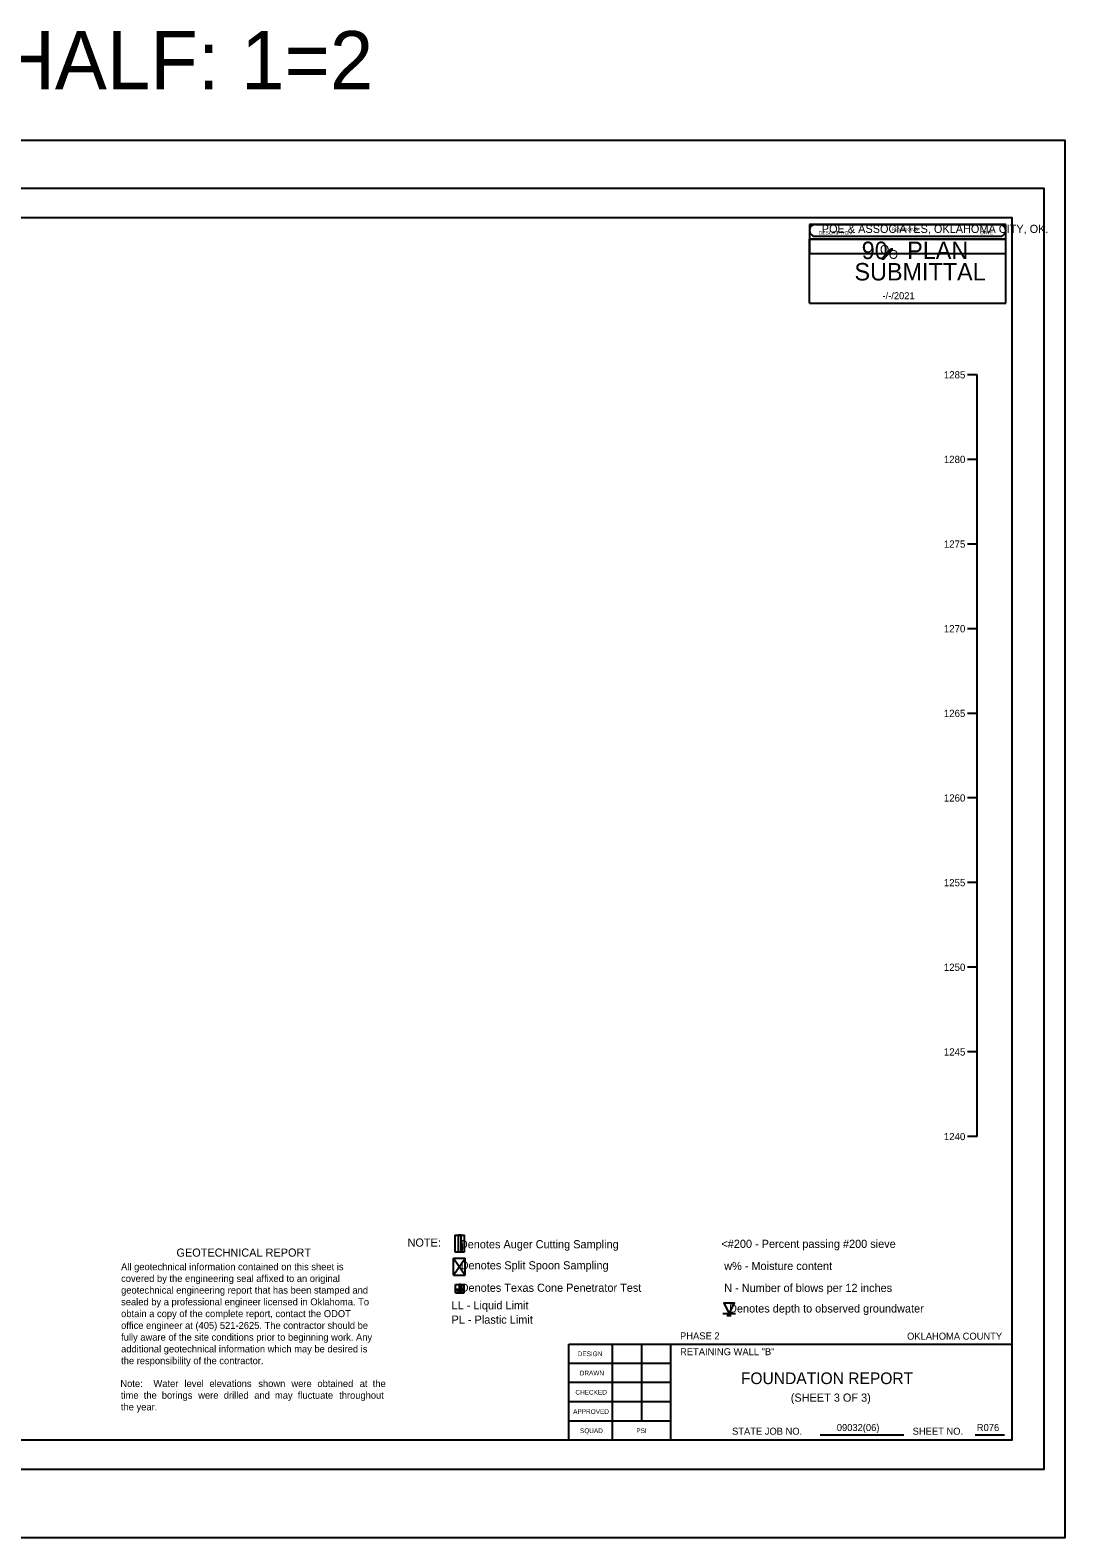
# Model space of a CAD drawing. Extents: x 7 to 126, y 24 to 56.
# Drawn here: x 107.93 to 125.68, y 30.33 to 56.22 of the extents above; entities that cross this region are included whole.
import ezdxf

# ---------------------------------------------------------------- set-up
doc = ezdxf.new("R2010")
doc.units = 0
for name, color, linetype in [('4', 7, 'Continuous'), ('S', 7, 'Continuous'), ('SHT_Plot_Shape_Full', 7, 'Continuous'), ('SHT_Plot_Shape_Half', 7, 'Continuous'), ('SHT_Sheet_Border', 7, 'Continuous'), ('SHT_Stamp_90_Submit', 7, 'Continuous'), ('SHT_Stamp_Rev_Block', 7, 'Continuous'), ('SHT_Standard_Sheet_Lines', 7, 'Continuous'), ('SHT_Standard_Sheet_Txt', 7, 'Continuous'), ('T', 7, 'Continuous'), ('T-5', 7, 'Continuous'), ('Text', 7, 'Continuous')]:
    doc.layers.add(name, color=color, linetype=linetype)

# ---------------------------------------------------------------- blocks, each defined once
blk = doc.blocks.new('DGRFC_WTLEV1_1')
for points in [[(-0.005, 0), (0.005, 0)], [(0, 0), (0.0042, 0.0083), (-0.0042, 0.0083), (0, 0)], [(-0.0017, -0.0017), (0.0017, -0.0017)]]:
    blk.add_lwpolyline(points)

msp = doc.modelspace()

# ---------------------------------------------------------------- linework, layer by layer
for p, q in [((124.178, 37.223), (124.178, 50.304)), ((115.214, 35.532), (115.214, 35.242))]:
    msp.add_line(p, q)
for points in [[(124.178, 50.304), (124.011, 50.304)], [(124.178, 48.851), (124.011, 48.851)], [(124.178, 47.397), (124.011, 47.397)], [(124.178, 45.944), (124.011, 45.944)], [(124.178, 44.49), (124.011, 44.49)], [(124.178, 43.037), (124.011, 43.037)], [(124.178, 41.583), (124.011, 41.583)], [(124.178, 40.13), (124.011, 40.13)], [(124.178, 38.676), (124.011, 38.676)], [(124.178, 37.223), (124.011, 37.223)], [(115.214, 35.532), (115.381, 35.532)], [(115.381, 35.242), (115.381, 35.532)], [(115.214, 35.242), (115.381, 35.242)], [(115.214, 35.242), (115.381, 35.242)]]:
    msp.add_lwpolyline(points)
for points in [[(115.272, 35.532), (115.272, 35.242), (115.322, 35.242), (115.322, 35.532)], [(115.337, 35.366), (115.331, 35.407), (115.322, 35.447), (115.337, 35.366)], [(115.322, 35.447), (115.322, 35.242), (115.337, 35.366), (115.322, 35.447)], [(115.322, 35.242), (115.337, 35.282), (115.337, 35.366), (115.322, 35.242)], [(115.322, 35.242), (115.331, 35.242), (115.337, 35.282), (115.322, 35.242)], [(115.337, 35.282), (115.339, 35.324), (115.337, 35.366), (115.337, 35.282)]]:
    msp.add_lwpolyline(points, close=True)
at = {"layer": 'SHT_Plot_Shape_Full'}
msp.add_lwpolyline([(89.683, 54.332), (125.683, 54.332), (125.683, 30.332), (89.683, 30.332)], close=True, dxfattribs=at)
at = {"layer": 'SHT_Plot_Shape_Half'}
msp.add_lwpolyline([(91.321, 53.507), (125.321, 53.507), (125.321, 31.507), (91.321, 31.507)], close=True, dxfattribs=at)
at = {"layer": 'SHT_Sheet_Border'}
for p, q in [((118.921, 32.007), (118.921, 33.658)), ((117.171, 32.007), (117.171, 33.657)), ((117.171, 33.657), (124.771, 33.657))]:
    msp.add_line(p, q, dxfattribs=at)
msp.add_lwpolyline([(93.271, 53.007), (124.771, 53.007), (124.771, 32.007), (93.271, 32.007)], close=True, dxfattribs=at)
at = {"layer": 'SHT_Stamp_90_Submit'}
for p, q in [((121.402, 52.883), (124.568, 52.883)), ((121.302, 52.633), (124.668, 52.633)), ((121.302, 51.534), (121.302, 52.633)), ((121.402, 52.683), (124.568, 52.683)), ((124.668, 51.534), (124.668, 52.633)), ((122.545, 52.295), (122.7, 52.467)), ((122.563, 52.295), (122.718, 52.467)), ((122.568, 52.295), (122.723, 52.467)), ((122.576, 52.295), (122.731, 52.467)), ((122.7, 52.467), (122.731, 52.467)), ((122.545, 52.295), (122.576, 52.295)), ((121.302, 51.534), (124.668, 51.534))]:
    msp.add_line(p, q, dxfattribs=at)
for centre, start, end in [((121.402, 52.783), 89.9952, 270), ((124.568, 52.783), 270, 90.0048)]:
    msp.add_arc(centre, 0.1, start, end, dxfattribs=at)
at = {"layer": 'SHT_Stamp_Rev_Block'}
for p, q in [((121.302, 52.883), (121.302, 52.383)), ((124.668, 52.883), (121.302, 52.883)), ((124.668, 52.383), (124.668, 52.883)), ((124.668, 52.633), (121.302, 52.633)), ((124.668, 52.383), (121.302, 52.383))]:
    msp.add_line(p, q, dxfattribs=at)
at = {"layer": 'SHT_Standard_Sheet_Lines'}
for p, q in [((117.921, 32.007), (117.921, 33.658)), ((118.421, 32.337), (118.421, 33.658)), ((121.482, 32.103), (122.922, 32.103)), ((124.146, 32.103), (124.649, 32.103))]:
    msp.add_line(p, q, dxfattribs=at)
for points in [[(118.921, 33.327), (117.171, 33.327)], [(118.921, 32.997), (117.171, 32.997)], [(118.921, 32.667), (117.171, 32.667)], [(118.921, 32.337), (117.171, 32.337)]]:
    msp.add_lwpolyline(points, dxfattribs=at)
at = {"layer": 'Text'}
for p, q in [((115.19, 34.841), (115.19, 35.134)), ((115.226, 34.542), (115.226, 34.682))]:
    msp.add_line(p, q, dxfattribs=at)
for points in [[(115.19, 34.841), (115.39, 35.134)], [(115.19, 35.134), (115.39, 34.841)], [(115.19, 35.134), (115.39, 35.134)], [(115.39, 34.841), (115.39, 35.134)], [(115.19, 34.841), (115.39, 34.841)], [(115.226, 34.682), (115.376, 34.682)], [(115.226, 34.542), (115.376, 34.542)], [(115.376, 34.542), (115.376, 34.682)]]:
    msp.add_lwpolyline(points, dxfattribs=at)
for points in [[(115.286, 34.598), (115.226, 34.598), (115.301, 34.542), (115.286, 34.598)], [(115.286, 34.598), (115.316, 34.682), (115.286, 34.682), (115.286, 34.598)], [(115.286, 34.598), (115.316, 34.598), (115.316, 34.682), (115.286, 34.598)], [(115.286, 34.598), (115.301, 34.542), (115.316, 34.598), (115.286, 34.598)], [(115.301, 34.542), (115.376, 34.598), (115.316, 34.598), (115.301, 34.542)]]:
    msp.add_lwpolyline(points, close=True, dxfattribs=at)

# ---------------------------------------------------------------- block references
at = {"layer": 'Text', "xscale": 21.6, "yscale": 21.6}
msp.add_blockref('DGRFC_WTLEV1_1', (119.922, 34.184), dxfattribs=at)

# ---------------------------------------------------------------- texts
for s, p in [('1285', (123.607, 50.242)), ('1280', (123.607, 48.789)), ('1275', (123.607, 47.335)), ('1270', (123.607, 45.882)), ('1265', (123.607, 44.428)), ('1260', (123.607, 42.975)), ('1255', (123.607, 41.521)), ('1250', (123.607, 40.068)), ('1245', (123.607, 38.614)), ('1240', (123.607, 37.161))]:
    msp.add_text(s, height=0.124).set_placement(p)
at = {"layer": '4'}
msp.add_text('FOUNDATION REPORT', height=0.2, dxfattribs=at).set_placement((120.124, 32.972))
at = {"layer": 'S'}
msp.add_text('FULL: 1=1   HALF: 1=2', height=1, dxfattribs=at).set_placement((99.989, 55.207))
at = {"layer": 'SHT_Stamp_90_Submit'}
for s, height, p in [('POE & ASSOCIATES, OKLAHOMA CITY, OK.', 0.14, (121.512, 52.74)), ('90   PLAN', 0.3, (122.197, 52.291)), ('O', 0.153, (122.511, 52.38)), ('O', 0.153, (122.662, 52.295)), ('SUBMITTAL', 0.3, (122.073, 51.924)), ('-/-/2021', 0.12, (122.553, 51.602))]:
    msp.add_text(s, height=height, dxfattribs=at).set_placement(p)
at = {"layer": 'SHT_Stamp_Rev_Block'}
for s, height, p in [('REVISIONS', 0.06, (122.71, 52.77)), ('DESCRIPTION', 0.05999, (121.462, 52.711)), ('DATE', 0.06, (124.231, 52.715))]:
    msp.add_text(s, height=height, dxfattribs=at).set_placement(p)
at = {"layer": 'SHT_Standard_Sheet_Txt'}
for s, height, p in [('DESIGN', 0.08, (117.323, 33.452)), ('DRAWN', 0.08, (117.358, 33.122)), ('CHECKED', 0.08, (117.284, 32.792)), ('APPROVED', 0.08, (117.245, 32.461)), ('SQUAD', 0.08, (117.362, 32.131)), ('PSI', 0.08, (118.329, 32.132)), ('STATE JOB NO.', 0.12, (119.972, 32.103)), ('SHEET NO. ', 0.12, (123.072, 32.103))]:
    msp.add_text(s, height=height, dxfattribs=at).set_placement(p)
at = {"layer": 'T'}
for s, p in [('PHASE 2', (119.08, 33.74)), ('OKLAHOMA COUNTY', (122.976, 33.735)), ('RETAINING WALL "B" ', (119.08, 33.468)), ('09032(06)', (121.77, 32.166)), ('R076', (124.173, 32.166))]:
    msp.add_text(s, height=0.12, dxfattribs=at).set_placement(p)
at = {"layer": 'T-5'}
msp.add_text('(SHEET 3 OF 3)', height=0.14, dxfattribs=at).set_placement((120.98, 32.67))
at = {"layer": 'Text'}
for s, height, p in [('NOTE:', 0.14, (114.403, 35.332)), ('GEOTECHNICAL REPORT', 0.14, (110.437, 35.16)), ('    Denotes Auger Cutting Sampling', 0.14, (115.092, 35.304)), (' <#200 - Percent passing #200 sieve', 0.14, (119.737, 35.311)), ('All geotechnical information contained on this sheet is ', 0.12, (109.487, 34.928)), ('    Denotes Split Spoon Sampling', 0.14, (115.106, 34.942)), ('w% - Moisture content', 0.14, (119.837, 34.931)), ('covered by the engineering seal affixed to an original ', 0.12, (109.487, 34.726)), ('    Denotes Texas Cone Penetrator Test', 0.14, (115.106, 34.557)), ('N - Number of blows per 12 inches', 0.14, (119.837, 34.554)), ('sealed by a professional engineer licensed in Oklahoma. To ', 0.12, (109.487, 34.324)), ('geotechnical engineering report that has been stamped and ', 0.12, (109.487, 34.526)), ('obtain a copy of the complete report, contact the ODOT ', 0.12, (109.487, 34.122)), (' LL - Liquid Limit', 0.14, (115.106, 34.255)), ('    Denotes depth to observed groundwater', 0.14, (119.713, 34.201)), ('office engineer at (405) 521-2625. The contractor should be ', 0.12, (109.487, 33.92)), (' PL - Plastic Limit', 0.14, (115.106, 34.009)), ('fully aware of the site conditions prior to beginning work. Any ', 0.12, (109.487, 33.718)), ('the responsibility of the contractor.', 0.12, (109.487, 33.314)), ('additional geotechnical information which may be desired is ', 0.12, (109.487, 33.516)), ('Note:', 0.12, (109.474, 32.922)), ('Water', 0.12, (110.042, 32.922)), ('level', 0.12, (110.575, 32.922)), ('elevations', 0.12, (111.003, 32.922)), ('shown', 0.12, (111.841, 32.922)), ('were', 0.12, (112.409, 32.922)), ('obtained', 0.12, (112.856, 32.922)), ('at', 0.12, (113.582, 32.922)), ('the ', 0.12, (113.805, 32.922)), ('time', 0.12, (109.484, 32.72)), ('the year.', 0.12, (109.484, 32.52)), ('the', 0.12, (109.876, 32.72)), ('borings', 0.12, (110.185, 32.72)), ('were', 0.12, (110.81, 32.72)), ('drilled', 0.12, (111.249, 32.72)), ('and', 0.12, (111.772, 32.72)), ('may', 0.12, (112.127, 32.72)), ('fluctuate', 0.12, (112.519, 32.72)), ('throughout ', 0.12, (113.229, 32.72))]:
    msp.add_text(s, height=height, dxfattribs=at).set_placement(p)

doc.saveas('drawing.dxf')
